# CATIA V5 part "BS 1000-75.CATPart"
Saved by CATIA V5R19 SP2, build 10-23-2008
Part number: BS 1000-75
Bounding box of the stored display mesh (mm): x -24.865 to 24.865, y -24.997 to 24.997, z 0 to 188
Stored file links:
  C:\Users\Bora\Desktop\3D Katı model\BS serisi\BS 1000\BS 1000-75.CATPart
  C:\Program Files\Dassault Systemes\B19\intel_a\reffiles\standard\MetricThickPitch.txt
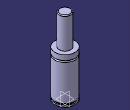
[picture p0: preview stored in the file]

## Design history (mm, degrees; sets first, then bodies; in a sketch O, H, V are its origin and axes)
Body1 (main body)
  Sketch1 on yz-plane, origin (0, 0, 0), H (0, 1, 0), V (0, 0, 1)
    point P2 (14, 186)
    line L1 (14, 186) -> (14, 112)
    point P3 (25, 99.5)
    line L2 (25, 112) -> (25, 99.5)
    point P6 (25, 95.5)
    line L3 (25, 95.5) -> (25, 7.5)
    line L4 (25, 4) -> (25, 0)
    point P9 (25, 95.5)
    point P10 (25, 99.5)
    arc A1 centre (25, 97.5) radius 2 from (25, 99.5) to (25, 95.5) ccw
    point P12 (14, 186)
    arc A2 centre (12, 186) radius 2 from (14, 186) to (12, 188) ccw
    line L5 (22.5, 7.5) -> (22.5, 4)
    line L6 (12, 188) -> (0, 188)
    point P15 (0, 188)
    line L7 (14, 112) -> (25, 112)
    line L8 (22.5, 7.5) -> (25, 7.5)
    line L9 (22.5, 4) -> (25, 4)
    line L10 (0, 0) -> (25, 0)
    coincidence: P15 V, P2 P12, P3 P10, P6 P9
    tangency: L6 A2
    horizontal: L7 H, L8 H, L9 H, L10 H
  Shaft1: profile Sketch1, axis Sketch1.V, angle 360
  Sketch2 on face of Shaft1 from Sketch1.L10, origin (0, 0, 0), H (1, 0, 0), V (0, -1, 0)
    point P1 (10, 0)
    distance P1 V = 10
  Hole1: placed by Sketch2, at (10, 0, 0) direction (0, 0, 1), diameter 6.647, depth 6, threaded "M8", thread diameter 8, thread depth 6, pitch 1.25
  CircPattern1: of Hole1, instances 2, angular step 180, axis from xy-plane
